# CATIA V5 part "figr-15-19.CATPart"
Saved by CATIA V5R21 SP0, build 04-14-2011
Part number: Part1
Bounding box of the stored display mesh (mm): x -46.56 to 46.56, y -36.965 to 25.965, z 0 to 40
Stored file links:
  D:\CATIA V5R21 E-RESOURCES\CATIA-V5R21\catia-v5r21-prt\c15-catia-v5r20-prt\c15-catia-v5r21-figr-15-19.CATPart
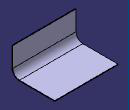
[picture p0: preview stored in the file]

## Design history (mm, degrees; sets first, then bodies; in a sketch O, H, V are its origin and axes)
SheetMetalParameters1: Thickness 1, BendRadius 1, KFactor 0.325257 {= log(min(100,max(20*SheetMetalParameters1.BendRadius,SheetMetalParameters1.Thickness)/SheetMetalParameters1.Thickness))/log(100)/2}, ReliefRadialLength 1, ReliefAxialLength 2, MinimumBendRadius 0
Body1 (main body)
  Sketch1 on xy-plane, origin (0, 0, 0), H (1, 0, 0), V (0, 1, 0)
    line L1 (-46.5596, 25.9646) -> (46.5596, 25.9646)
    line L2 (46.5596, 25.9646) -> (46.5596, -25.9646)
    line L3 (46.5596, -25.9646) -> (-46.5596, -25.9646)
    line L4 (-46.5596, -25.9646) -> (-46.5596, 25.9646)
    horizontal: L1 H, L3 H
    vertical: L2 V, L4 V
    symmetry: L1 L3 H, L4 L2 V
  Wall1: Thickness 1, Profile Sketch1
  d_NewWallOnEdge1: NewWallOnEdge_Edge edge [face of Wall1 | face of Wall1], NewWallOnEdge_Length 40, NewWallOnEdge_HeightLimitOffset 0, NewWallOnEdge_WidthOffset1 0, NewWallOnEdge_WidthOffset2 0, NewWallOnEdge_Angle 90, NewWallOnEdge_BendRadiusValue 10 {= d_NewWallOnEdge1.Clearance}, NewWallOnEdge_BendTable SheetMetalParameters1, KFacteur 0.5 {= log(min(100,max(20*d_NewWallOnEdge1.Radius,SheetMetalParameters1.Thickness)/SheetMetalParameters1.Thickness))/log(100)/2}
